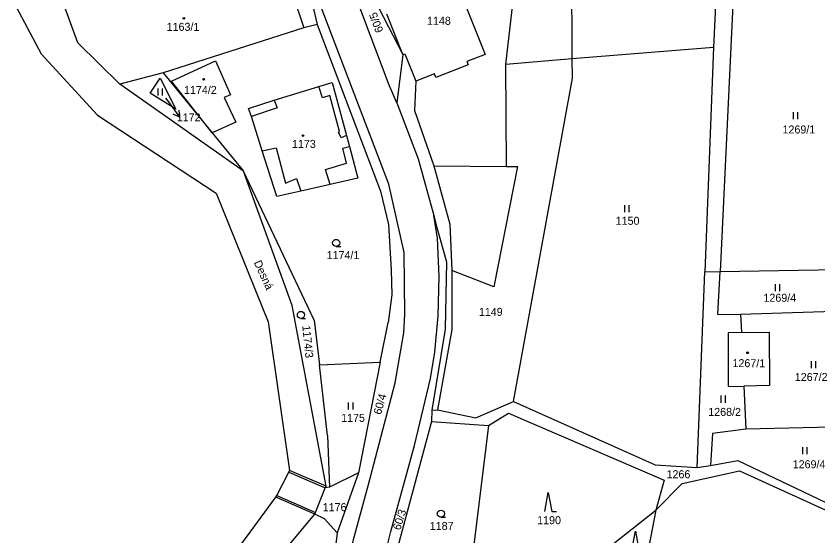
# Model space of a CAD drawing. Extents: x -670359 to -668019, y -978807 to -976674.
# Drawn here: x -670237.2 to -670066.9, y -978053.2 to -977942.9 of the extents above; entities that cross this region are included whole.
import ezdxf

# ---------------------------------------------------------------- set-up
doc = ezdxf.new("R2010")
doc.units = 0
for name, color, linetype in [('Hranice kat_území', 7, 'Continuous'), ('Hranice parcel', 7, 'Continuous'), ('Parcelní čísla', 7, 'Continuous'), ('Pop  PČ popisy', 7, 'Continuous'), ('Vnitřní kresba', 7, 'Continuous'), ('Značky budov', 7, 'Continuous'), ('Značky kultur', 7, 'Continuous')]:
    doc.layers.add(name, color=color, linetype=linetype)

msp = doc.modelspace()

# ---------------------------------------------------------------- linework, layer by layer
at = {"layer": 'Hranice kat_území'}
for points in [[(-670237.25, -977940.88), (-670231.88, -977950.91)], [(-670231.88, -977950.91), (-670219.96, -977963.92)], [(-670219.96, -977963.92), (-670194.71, -977980.48)], [(-670194.71, -977980.48), (-670183.71, -978007.78)], [(-670183.71, -978007.78), (-670179.14, -978039.33)], [(-670181.84, -978044.64), (-670179.32, -978039.69)], [(-670179.32, -978039.69), (-670179.14, -978039.33)], [(-670206.64, -978078.45), (-670182.02, -978044.99)], [(-670182.02, -978044.99), (-670181.84, -978044.64)]]:
    msp.add_lwpolyline(points, dxfattribs=at)
at = {"layer": 'Hranice parcel'}
for points in [[(-670156.36, -977961.27), (-670157.99, -977957.53), (-670177.75, -977905.2), (-670177.61, -977904.51)], [(-670172.63, -978082.94), (-670171.28, -978083.15), (-670170.18, -978076.11), (-670165.52, -978053.97), (-670162.38, -978042.27), (-670156.72, -978020.75), (-670154.86, -978010.1), (-670154.63, -978006.17), (-670154.76, -977993.05), (-670158.01, -977978.52), (-670176.81, -977929.42)], [(-670176.81, -977929.42), (-670173.29, -977944.67)], [(-670180.87, -977931.18), (-670176.09, -977945.37)], [(-670224.12, -977948.54), (-670229.61, -977933.38)], [(-670164.29, -977933.2), (-670155.09, -977951.04)], [(-670119.06, -977951.97), (-670119.19, -977933.05)], [(-670088.41, -977935.95), (-670089.06, -977949.54)], [(-670084.73, -977935.93), (-670087.67, -977997.06)], [(-670133.18, -977953.11), (-670131.39, -977937.69)], [(-670173.29, -977944.67), (-670176.09, -977945.37)], [(-670173.29, -977944.67), (-670159.81, -977980.06)], [(-670176.09, -977945.37), (-670206.01, -977954.92)], [(-670215.17, -977957.33), (-670224.12, -977948.54)], [(-670089.06, -977949.54), (-670090.92, -977997.12)], [(-670155.09, -977951.04), (-670156.36, -977961.27)], [(-670155.09, -977951.04), (-670154.65, -977950.86)], [(-670154.65, -977950.86), (-670152.33, -977956.66)], [(-670204.19, -977956.66), (-670194.84, -977952.38), (-670191.69, -977959.57), (-670193, -977960.14), (-670190.54, -977965.39), (-670195.59, -977967.63)], [(-670133.01, -977974.79), (-670133.18, -977953.11)], [(-670119.03, -977956.01), (-670119.06, -977951.97)], [(-670206.01, -977954.92), (-670195.59, -977967.63)], [(-670208.76, -977959.22), (-670206.66, -977956.04)], [(-670206.66, -977956.04), (-670203.27, -977962.62)], [(-670195.59, -977967.63), (-670204.19, -977956.66)], [(-670152.33, -977956.66), (-670152.61, -977962.89)], [(-670131.57, -978024.69), (-670119.03, -977956.01)], [(-670188.93, -977975.76), (-670215.17, -977957.33)], [(-670182.37, -977960.69), (-670172.9, -977957.79)], [(-670172.9, -977957.79), (-670170.09, -977956.93)], [(-670170.09, -977956.93), (-670167.06, -977968.23)], [(-670203.27, -977962.62), (-670208.76, -977959.22)], [(-670187.83, -977962.47), (-670182.37, -977960.69)], [(-670156.36, -977961.27), (-670151.81, -977973.14)], [(-670187.25, -977964.17), (-670187.83, -977962.47)], [(-670152.61, -977962.89), (-670148.46, -977974.68)], [(-670184.92, -977971.47), (-670187.25, -977964.17)], [(-670195.59, -977967.63), (-670188.93, -977975.76)], [(-670167.06, -977968.23), (-670166.43, -977970.55)], [(-670181.82, -977981.14), (-670184.92, -977971.47)], [(-670166.43, -977970.55), (-670164.6, -977977.27)], [(-670151.81, -977973.14), (-670148.49, -977985.18)], [(-670148.46, -977974.68), (-670133.01, -977974.79)], [(-670178.55, -978004.33), (-670188.93, -977975.76)], [(-670173.87, -978007.38), (-670188.93, -977975.76)], [(-670170.5, -977978.6), (-670176.74, -977980)], [(-670164.6, -977977.27), (-670170.5, -977978.6)], [(-670176.74, -977980), (-670181.82, -977981.14)], [(-670159.81, -977980.06), (-670158.11, -977987.11)], [(-670163.67, -978098.07), (-670164.62, -978097.52), (-670164.93, -978097), (-670165.03, -978095.83), (-670164.26, -978085.83), (-670163.16, -978077.87), (-670159.11, -978058.23), (-670157.62, -978052.26), (-670152.59, -978034.05), (-670149.21, -978019.82), (-670148.28, -978014.22), (-670147.57, -978006.49), (-670147.34, -977998.17), (-670147.68, -977989.98), (-670148.49, -977985.18)], [(-670148.49, -977985.18), (-670147.83, -977987.72)], [(-670158.11, -977987.11), (-670157.54, -977996.79)], [(-670147.83, -977987.72), (-670145.77, -977995.05)], [(-670145.77, -977995.05), (-670146.04, -978009.36)], [(-670157.54, -977996.79), (-670157.43, -978002.07)], [(-670092.54, -978038.69), (-670090.92, -977997.12)], [(-670090.92, -977997.12), (-670087.67, -977997.06)], [(-670088.11, -978006.19), (-670087.67, -977997.06)], [(-670087.67, -977997.06), (-670058.53, -977996.56)], [(-670157.43, -978002.07), (-670158.19, -978007.91)], [(-670171.39, -978042.65), (-670178.55, -978004.33)], [(-670088.11, -978006.19), (-670083.31, -978006.16)], [(-670083.31, -978006.16), (-670058.93, -978005.38)], [(-670083.31, -978006.16), (-670083.13, -978010.04)], [(-670173.87, -978007.38), (-670172.79, -978016.92)], [(-670159.86, -978016.35), (-670158.19, -978007.91)], [(-670146.04, -978009.36), (-670148.89, -978026.54)], [(-670085.93, -978010.09), (-670085.95, -978021.52)], [(-670083.13, -978010.04), (-670085.93, -978010.09)], [(-670083.13, -978010.04), (-670077.21, -978009.96)], [(-670077.21, -978009.96), (-670077.15, -978021.31)], [(-670172.79, -978016.92), (-670159.86, -978016.35)], [(-670159.86, -978016.35), (-670164.52, -978039.85)], [(-670171.1, -978031.88), (-670172.79, -978016.92)], [(-670085.95, -978021.52), (-670082.62, -978021.44)], [(-670077.15, -978021.31), (-670082.62, -978021.44)], [(-670082.62, -978021.44), (-670082.22, -978030.53)], [(-670139.57, -978028.13), (-670131.57, -978024.69)], [(-670131.57, -978024.69), (-670101.43, -978038.09)], [(-670148.89, -978026.54), (-670148.99, -978028.93)], [(-670148.89, -978026.54), (-670147.69, -978026.47)], [(-670147.69, -978026.47), (-670139.57, -978028.13)], [(-670136.86, -978029.74), (-670132.64, -978027.16)], [(-670132.64, -978027.16), (-670099.57, -978041.37)], [(-670148.99, -978028.93), (-670159.63, -978068.36)], [(-670148.99, -978028.93), (-670136.86, -978029.74)], [(-670136.86, -978029.74), (-670140.01, -978055.12)], [(-670057.91, -978029.98), (-670082.22, -978030.53)], [(-670089.25, -978031.45), (-670089.69, -978038.25)], [(-670082.22, -978030.53), (-670089.25, -978031.45)], [(-670171.1, -978031.88), (-670170.63, -978042.84)], [(-670101.43, -978038.09), (-670092.54, -978038.69)], [(-670092.54, -978038.69), (-670089.69, -978038.25)], [(-670089.69, -978038.25), (-670083.87, -978037.17)], [(-670083.87, -978037.17), (-670056, -978050.5)], [(-670164.52, -978039.85), (-670170.63, -978042.84)], [(-670164.52, -978039.85), (-670168.99, -978052.57)], [(-670095.74, -978042.12), (-670083.53, -978039.41)], [(-670083.53, -978039.41), (-670053.47, -978053.05)], [(-670099.57, -978041.37), (-670101.33, -978047.75)], [(-670173.6, -978048.25), (-670171.55, -978043.02)], [(-670171.55, -978043.02), (-670171.39, -978042.65)], [(-670170.63, -978042.84), (-670171.55, -978043.02)], [(-670101.33, -978047.75), (-670095.74, -978042.12)], [(-670196.85, -978076.29), (-670173.76, -978048.61)], [(-670173.76, -978048.61), (-670173.6, -978048.25)], [(-670171.72, -978049.59), (-670173.76, -978048.61)], [(-670123.1, -978064.97), (-670101.33, -978047.75)], [(-670101.33, -978047.75), (-670103.12, -978057.29)], [(-670168.99, -978052.57), (-670171.72, -978049.59)], [(-670168.99, -978052.57), (-670172.53, -978081.22)]]:
    msp.add_lwpolyline(points, dxfattribs=at)
at = {"layer": 'Parcelní čísla'}
for p, q in [((-670205.49, -977960.3), (-670204.89, -977961.1)), ((-670202.68, -977962.82), (-670202.5, -977964.31))]:
    msp.add_line(p, q, dxfattribs=at)
msp.add_lwpolyline([(-670204.89, -977961.1), (-670202.5, -977964.31), (-670203.88, -977963.71)], dxfattribs=at)
at = {"layer": 'Vnitřní kresba'}
for points in [[(-670145.58, -977931.03), (-670137.56, -977951)], [(-670155.09, -977951.04), (-670158.47, -977942.46)], [(-670089.06, -977949.54), (-670119.06, -977951.97)], [(-670137.56, -977951), (-670141.45, -977952.49)], [(-670141.18, -977953.22), (-670148.08, -977955.89)], [(-670141.45, -977952.49), (-670141.18, -977953.22)], [(-670119.06, -977951.97), (-670133.18, -977953.11)], [(-670206.01, -977954.92), (-670215.17, -977957.33)], [(-670148.37, -977955.14), (-670152.33, -977956.66)], [(-670148.08, -977955.89), (-670148.37, -977955.14)], [(-670172.12, -977960.2), (-670172.9, -977957.79)], [(-670170.6, -977959.73), (-670172.12, -977960.2)], [(-670168.5, -977967.4), (-670170.6, -977959.73)], [(-670182.37, -977960.69), (-670181.74, -977962.37)], [(-670181.74, -977962.37), (-670187.25, -977964.17)], [(-670168.73, -977967.5), (-670168.5, -977967.4)], [(-670168.18, -977968.7), (-670168.73, -977967.5)], [(-670167.06, -977968.23), (-670168.18, -977968.7)], [(-670184.92, -977971.47), (-670182, -977970.84)], [(-670182, -977970.84), (-670180.01, -977978.3)], [(-670167.84, -977970.9), (-670166.43, -977970.55)], [(-670167.06, -977974.07), (-670167.84, -977970.9)], [(-670171.5, -977975.4), (-670167.06, -977974.07)], [(-670170.5, -977978.6), (-670171.5, -977975.4)], [(-670148.46, -977974.68), (-670145.1, -977987.02)], [(-670130.69, -977974.8), (-670135.76, -978000.36)], [(-670133.01, -977974.79), (-670130.69, -977974.8)], [(-670180.01, -977978.3), (-670177.68, -977977.35)], [(-670177.68, -977977.35), (-670176.74, -977980)], [(-670145.1, -977987.02), (-670144.62, -977996.86)], [(-670144.62, -977996.86), (-670144.68, -978009.37)], [(-670135.76, -978000.36), (-670144.62, -977996.86)], [(-670144.68, -978009.37), (-670147.69, -978026.47)], [(-670179.32, -978039.69), (-670171.55, -978043.02)], [(-670171.39, -978042.65), (-670179.14, -978039.33)], [(-670173.76, -978048.61), (-670182.02, -978044.99)], [(-670181.84, -978044.64), (-670173.6, -978048.25)]]:
    msp.add_lwpolyline(points, dxfattribs=at)
at = {"layer": 'Značky budov'}
for centre in [(-670201.58, -977943.34), (-670197.4, -977956.27), (-670176.26, -977968.25), (-670081.82, -978014.34)]:
    msp.add_circle(centre, 0.175, dxfattribs=at)
at = {"layer": 'Značky kultur'}
for p, q in [((-670207.12, -977958.25), (-670207.12, -977959.75)), ((-670206.12, -977959.75), (-670206.12, -977958.25)), ((-670072.13, -977963.24), (-670072.13, -977964.74)), ((-670071.13, -977964.74), (-670071.13, -977963.24)), ((-670107.98, -977982.97), (-670107.98, -977984.47)), ((-670106.98, -977984.47), (-670106.98, -977982.97)), ((-670169.23, -977991.76), (-670168.23, -977991.76)), ((-670075.97, -977999.78), (-670075.97, -978001.28)), ((-670074.97, -978001.28), (-670074.97, -977999.78)), ((-670176.73, -978007.05), (-670175.73, -978007.05)), ((-670068.28, -978016.13), (-670068.28, -978017.63)), ((-670067.28, -978017.63), (-670067.28, -978016.13)), ((-670166.65, -978024.9), (-670166.65, -978026.4)), ((-670165.65, -978026.4), (-670165.65, -978024.9)), ((-670087.51, -978023.44), (-670087.51, -978024.94)), ((-670086.51, -978024.94), (-670086.51, -978023.44)), ((-670070.17, -978034.38), (-670070.17, -978035.88)), ((-670069.17, -978035.88), (-670069.17, -978034.38)), ((-670146.98, -978049.24), (-670145.98, -978049.24))]:
    msp.add_line(p, q, dxfattribs=at)
for points in [[(-670124.91, -978048.02), (-670124.16, -978044.02), (-670123.41, -978048.02), (-670122.41, -978048.02)], [(-670106.41, -978056.23), (-670105.66, -978052.23), (-670104.91, -978056.23), (-670103.91, -978056.23)]]:
    msp.add_lwpolyline(points, dxfattribs=at)
for centre, radius in [((-670201.58, -977943.34), 0.175), ((-670197.4, -977956.27), 0.175), ((-670176.26, -977968.25), 0.175), ((-670169.23, -977991.01), 0.75), ((-670176.73, -978006.3), 0.75), ((-670081.82, -978014.34), 0.175), ((-670146.98, -978048.49), 0.75)]:
    msp.add_circle(centre, radius, dxfattribs=at)

# ---------------------------------------------------------------- texts
at = {"layer": 'Parcelní čísla'}
for s, rotation, p in [('60/5', 110.1673, (-670159.17, -977946.03)), ('1174/3', 275.7862, (-670176.44, -978008.61)), ('1267/1', 359.4881, (-670085.03, -978017.37)), ('60/4', 74.1647, (-670159.72, -978027.59)), ('60/3', 72.2639, (-670155.64, -978052.12))]:
    msp.add_text(s, height=1.7, rotation=rotation, dxfattribs=at).set_placement(p)
for s, height, p in [('1148', 1.7, (-670149.93, -977944.72)), ('1163/1', 1.7, (-670205.25, -977946)), ('1174/2', 1.7, (-670201.56, -977959.4)), ('1172', 0.1, (-670205.49, -977960.3)), ('1172', 1.7, (-670203.1, -977965.21)), ('1269/1', 1.7, (-670074.39, -977967.79)), ('1173', 1.7, (-670178.62, -977970.85)), ('1150', 1.7, (-670109.84, -977987.17)), ('1174/1', 1.7, (-670171.25, -977994.45)), ('1269/4', 1.7, (-670078.44, -978003.51)), ('1149', 1.7, (-670138.91, -978006.5)), ('1267/2', 1.7, (-670071.78, -978020.33)), ('1268/2', 1.7, (-670090.17, -978027.74)), ('1175', 1.7, (-670168.17, -978029)), ('1269/4', 1.7, (-670072.23, -978038.85)), ('1266', 1.7, (-670099.03, -978040.97)), ('1176', 1.7, (-670172.09, -978047.96)), ('1187', 1.7, (-670149.34, -978051.94)), ('1190', 1.7, (-670126.52, -978050.72))]:
    msp.add_text(s, height=height, dxfattribs=at).set_placement(p)
at = {"layer": 'Pop  PČ popisy'}
msp.add_text('Desná', height=1.7, rotation=294.7156, dxfattribs=at).set_placement((-670186.77, -977995.18))

doc.saveas('drawing.dxf')
